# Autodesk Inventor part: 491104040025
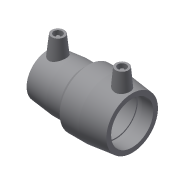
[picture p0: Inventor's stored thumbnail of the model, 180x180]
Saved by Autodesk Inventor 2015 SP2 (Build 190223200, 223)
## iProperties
Created: 2017-06
Part Number: 491104040025
Material: Generic
Description: PLASSON REDUCING COUPLER 40-25
Document SubType Name: Modeling
Designer: KIM
Mass: 54.8237 g
Surface Area: 155.252 cm^2
Volume: 54.8237 cm^3
Density: 1 g/cm^3
Appearance: Default
Author: KIM
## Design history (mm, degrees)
derived "491104.ipt"
feature "Solid1::491104.ipt"
tag "TaggingFeature1"
body "Solid1"
other parameters: "d2" = 37, "d4" = 24, "d5" = 33.3, "d7" = 25, "d8" = 168 deg, "d10" = 16, "d11" = 5.33333, "d14" = 17.6296, "d18" = 25, "d19" = 2, "d20" = 168 deg, "d22" = 108.92847, "d25" = 135 deg, "d29" = 38, "d30" = 15, "d31" = 31.5, "d34" = 6 deg, "d35" = 15, "d38" = 24.25, "d39" = 5 deg, "d41" = 4, "d42" = 14, "d43" = 0, "d45" = 4, "d46" = 14, "d47" = 0, "d48" = 37, "d50" = 56, "d52" = 22.5, "d53" = 17.6, "d54" = 5.86667, "d55" = 168 deg, "d56" = 26.4, "d57" = 44, "d58" = 50.4, "d59" = 2, "d60" = 135 deg, "d61" = 47, "d62" = 15, "d64" = 4, "d66" = 5 deg, "d67" = 14, "d68" = 0, "d69" = 31.5, "d70" = 37, "d71" = 56, "d73" = 52.64, "d76" = 2, "d77" = 168 deg, "d79" = 2, "d80" = 44, "d81" = 22.5, "d82" = 34.78, "d83" = 120 deg, "d88" = 15, "d89" = 25, "d90" = 5 deg, "d92" = 4, "d93" = 14, "d94" = 0, "d95" = 3, "d96" = 0, "d97" = 3, "d98" = 0, "d99" = 11.6, "d100" = 2.9, "d101" = 33.7366, "d102" = 20 deg, "d103" = 12.76, "d104" = 3.19, "d105" = 51.0608, "d106" = 3.60705, "d107" = 3, "d108" = 0, "d109" = 3, "d110" = 0, "d_1" = 25, "D_1" = 37, "A_1" = 38, "d_2" = 12, "L_1" = 44, "A_" = 47, "D_" = 56
